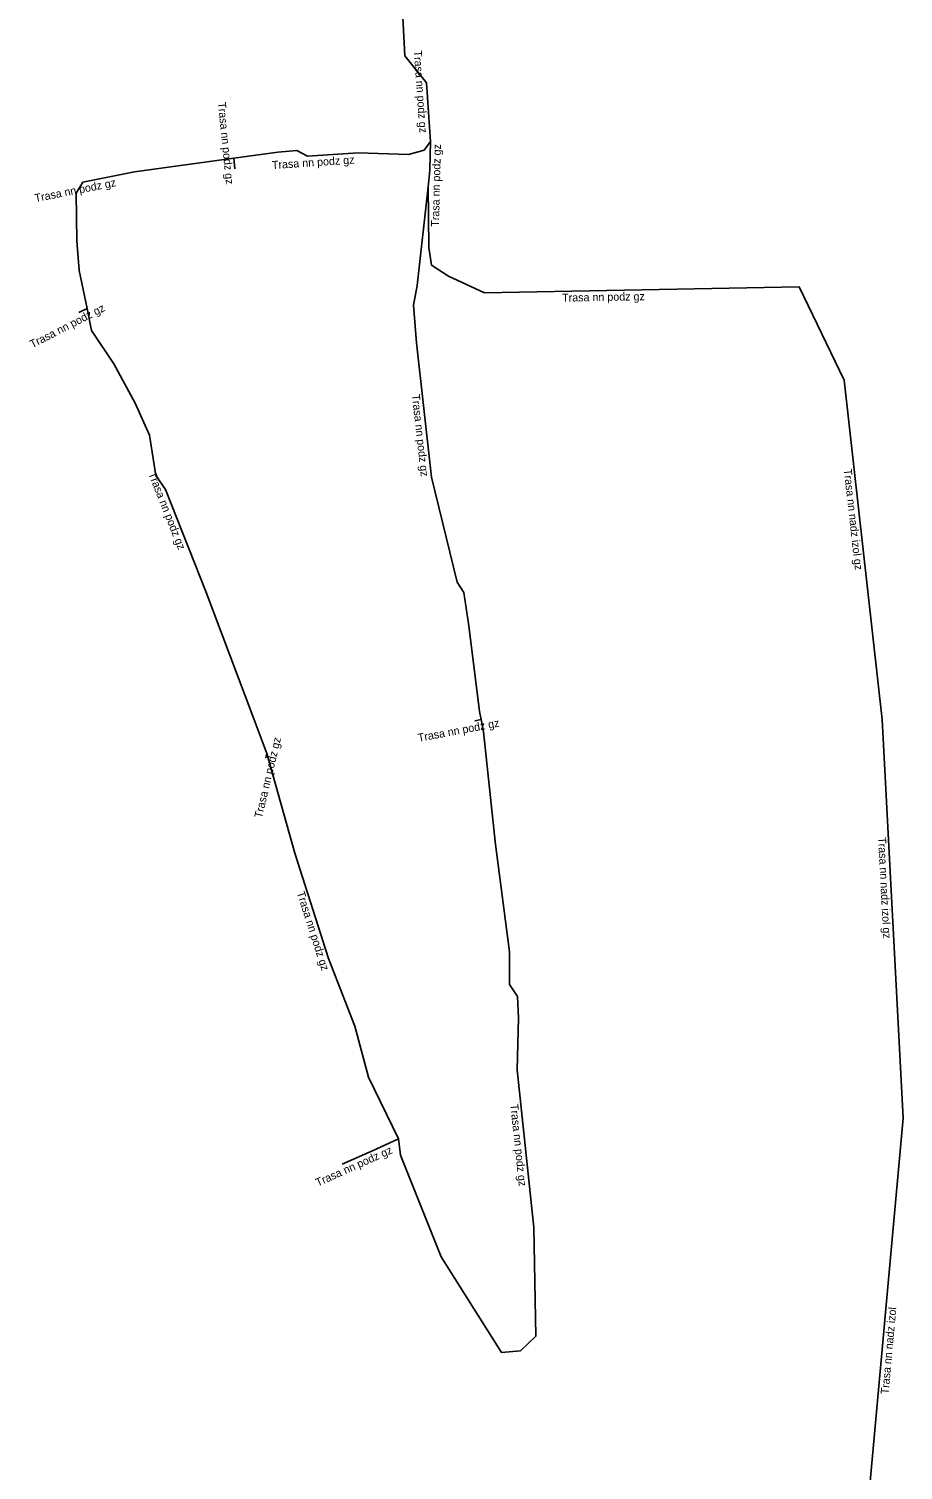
# Model space of a CAD drawing. Extents: x -745887 to -745704, y -1028211 to -1027575.
# Drawn here: x -745791.2 to -745736.6, y -1027981.9 to -1027891.8 of the extents above; entities that cross this region are included whole.
import ezdxf

# ---------------------------------------------------------------- set-up
doc = ezdxf.new("R2010")
doc.units = 0
doc.layers.add('Popiskový text - Ostatní atributy Trasy', color=7, linetype='Continuous')
doc.layers.add('Spojnice NN', color=7, linetype='Continuous')

msp = doc.modelspace()

# ---------------------------------------------------------------- linework, layer by layer
at = {"layer": 'Spojnice NN'}
for points in [[(-745766.338, -1027895.199), (-745767.686, -1027893.529), (-745767.896, -1027889.46), (-745768.314, -1027884.724), (-745768.318, -1027882.718)], [(-745766.078, -1027898.883), (-745766.338, -1027895.199)], [(-745778.363, -1027899.917), (-745775.619, -1027899.535), (-745774.436, -1027899.44), (-745773.775, -1027899.798), (-745770.6, -1027899.585), (-745767.465, -1027899.694), (-745766.488, -1027899.413), (-745766.078, -1027898.883)], [(-745766.236, -1027901.705), (-745766.121, -1027900.656), (-745766.078, -1027898.883)], [(-745778.363, -1027899.917), (-745784.574, -1027900.773), (-745787.793, -1027901.415), (-745788.215, -1027902.098), (-745788.178, -1027905.081), (-745788.018, -1027906.928), (-745787.535, -1027909.308)], [(-745778.297, -1027900.577), (-745778.363, -1027899.917)], [(-745762.922, -1027934.995), (-745763.016, -1027934.498), (-745763.688, -1027929.137), (-745763.996, -1027927.05), (-745764.416, -1027926.418), (-745766.025, -1027919.851), (-745766.957, -1027911.459), (-745767.156, -1027909.094), (-745766.912, -1027907.871), (-745766.236, -1027901.705)], [(-745766.236, -1027901.705), (-745766.193, -1027905.494), (-745766.021, -1027906.612), (-745764.969, -1027907.291), (-745762.717, -1027908.326), (-745743.059, -1027907.964), (-745740.25, -1027913.79)], [(-745787.535, -1027909.308), (-745788.043, -1027909.57)], [(-745787.535, -1027909.308), (-745787.256, -1027910.681), (-745785.863, -1027912.772), (-745784.525, -1027915.228), (-745783.641, -1027917.217), (-745783.232, -1027919.747), (-745782.631, -1027920.621), (-745780.109, -1027926.997), (-745777.184, -1027934.791), (-745776.311, -1027937.116)], [(-745740.25, -1027913.79), (-745737.871, -1027935.005)], [(-745768.088, -1027961.212), (-745767.963, -1027962.214), (-745765.414, -1027968.584), (-745761.65, -1027974.557), (-745760.467, -1027974.442), (-745759.498, -1027973.537), (-745759.633, -1027966.748), (-745760.682, -1027956.897), (-745760.584, -1027953.646), (-745760.652, -1027952.313), (-745761.145, -1027951.566), (-745761.154, -1027949.516), (-745761.791, -1027944.562), (-745762.021, -1027942.808), (-745762.775, -1027935.763), (-745762.922, -1027934.995)], [(-745762.922, -1027934.995), (-745763.318, -1027935.07)], [(-745737.871, -1027935.005), (-745736.568, -1027959.904)], [(-745776.311, -1027937.116), (-745776.377, -1027937.393)], [(-745776.311, -1027937.116), (-745774.547, -1027943.357), (-745772.445, -1027949.927), (-745770.814, -1027954.163), (-745769.949, -1027957.356), (-745768.088, -1027961.212)], [(-745736.568, -1027959.904), (-745738.898, -1027985.605)], [(-745768.088, -1027961.212), (-745769.48, -1027961.846), (-745771.594, -1027962.793)]]:
    msp.add_lwpolyline(points, dxfattribs=at)

# ---------------------------------------------------------------- texts
at = {"layer": 'Popiskový text - Ostatní atributy Trasy'}
for s, rotation, p in [('Trasa nn podz gz', 274.03698, (-745767.13, -1027893.203)), ('Trasa nn podz gz', 275.71059, (-745779.364, -1027896.437)), ('Trasa nn podz gz', 88.6107, (-745765.556, -1027904.205)), ('Trasa nn podz gz', 3.83803, (-745775.972, -1027900.597)), ('Trasa nn podz gz', 11.27912, (-745790.757, -1027902.669)), ('Trasa nn podz gz', 1.05498, (-745757.86, -1027908.887)), ('Trasa nn podz gz', 27.28233, (-745790.952, -1027911.802)), ('Trasa nn podz gz', 276.33719, (-745767.251, -1027914.697)), ('Trasa nn podz gz', 291.58107, (-745783.72, -1027919.636)), ('Trasa nn nadz izol gz', 276.39828, (-745740.279, -1027919.366)), ('Trasa nn podz gz', 10.72445, (-745766.825, -1027936.396)), ('Trasa nn podz gz', 76.59818, (-745776.614, -1027941.193)), ('Trasa nn nadz izol gz', 272.99564, (-745738.137, -1027942.359)), ('Trasa nn podz gz', 287.74151, (-745774.442, -1027945.819)), ('Trasa nn podz gz', 276.07833, (-745761.107, -1027959.05)), ('Trasa nn podz gz', 24.13075, (-745773.127, -1027964.192)), ('Trasa nn nadz izol', 84.821, (-745737.481, -1027977.185))]:
    msp.add_text(s, height=0.5, rotation=rotation, dxfattribs=at).set_placement(p)

doc.saveas('drawing.dxf')
